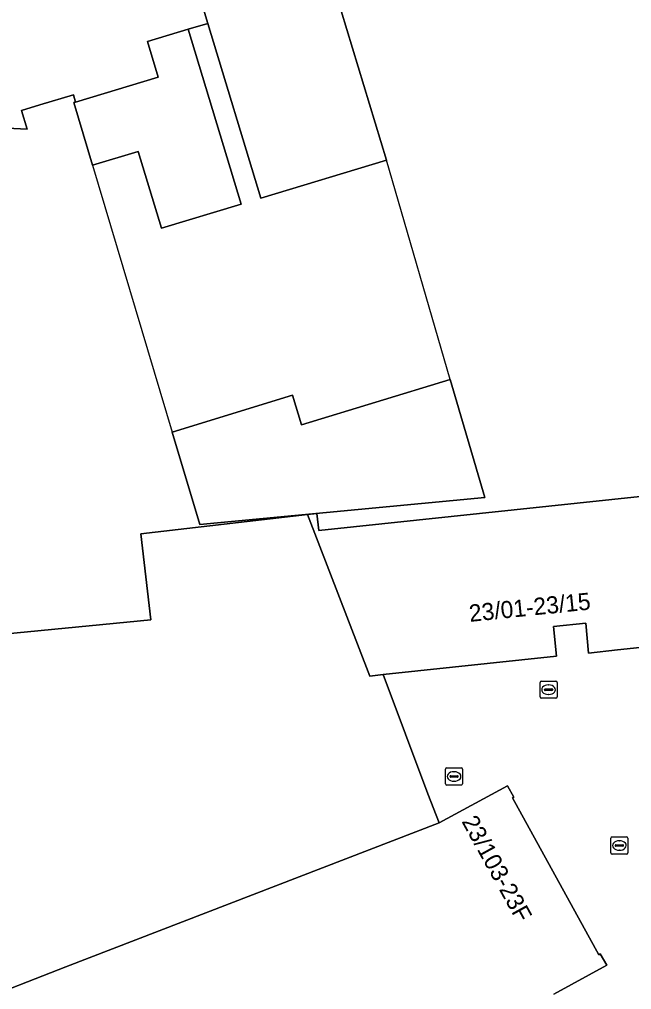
# Model space of a CAD drawing. Extents: x 161087 to 161926, y 382572 to 383873.
# Drawn here: x 161757.6 to 161793.5, y 382757.7 to 382814.4 of the extents above; entities that cross this region are included whole.
import ezdxf

# ---------------------------------------------------------------- set-up
doc = ezdxf.new("R2010")
doc.units = 0
for name, color, linetype in [('IMGEO_Brandkraan', 7, 'Continuous'), ('IMGEO_Erf', 7, 'Continuous'), ('IMGEO_Kolk', 7, 'Continuous'), ('IMGEO_Pand', 7, 'Continuous'), ('IMGEO_Pand_nummerreeks', 7, 'Continuous'), ('IMGEO_Pand_overbouw', 7, 'Continuous')]:
    doc.layers.add(name, color=color, linetype=linetype)

msp = doc.modelspace()

# ---------------------------------------------------------------- linework, layer by layer
at = {"layer": 'IMGEO_Brandkraan'}
for p, q in [((161782.57, 382769.723), (161782.57, 382770.575)), ((161782.645, 382770.649), (161783.497, 382770.649)), ((161783.571, 382770.575), (161783.571, 382769.723)), ((161782.829, 382770.143), (161782.829, 382770.155)), ((161783.267, 382770.106), (161782.869, 382770.106)), ((161782.872, 382770.192), (161783.27, 382770.192)), ((161783.058, 382770.429), (161783.083, 382770.429)), ((161783.313, 382770.155), (161783.313, 382770.143)), ((161783.497, 382769.649), (161782.645, 382769.649)), ((161783.081, 382769.869), (161783.056, 382769.869))]:
    msp.add_line(p, q, dxfattribs=at)
for points in [[(161782.57, 382769.723), (161782.57, 382770.575)], [(161782.645, 382770.649), (161783.497, 382770.649)], [(161783.571, 382770.575), (161783.571, 382769.723)], [(161783.497, 382769.649), (161782.645, 382769.649)]]:
    msp.add_lwpolyline(points, dxfattribs=at)
for centre, radius, start, end in [((161782.647, 382770.573), 0.0765, 91.552, 178.448), ((161782.647, 382770.573), 0.0765, 91.552, 178.448), ((161783.495, 382770.573), 0.0765, 1.552, 88.448), ((161783.495, 382770.573), 0.0765, 1.552, 88.448), ((161782.869, 382770.152), 0.0403, 85.8775, 175.7526), ((161782.866, 382770.142), 0.0366, 178.938, 274.7102), ((161783.27, 382770.149), 0.043, 264.8664, 352.4533), ((161783.274, 382770.154), 0.0386, 1.7309, 96.639), ((161782.647, 382769.725), 0.0765, 181.552, 268.448), ((161782.647, 382769.725), 0.0765, 181.552, 268.448), ((161783.495, 382769.725), 0.0765, 271.552, 358.448), ((161783.495, 382769.725), 0.0765, 271.552, 358.448)]:
    msp.add_arc(centre, radius, start, end, dxfattribs=at)
for centre, major_axis, ratio, start_param, end_param in [((161783.057, 382770.149), (-0.387, 0.002), 0.722429, 4.712389, 7.853982), ((161783.082, 382770.149), (-0.39, 0.002), 0.717154, 1.570796, 4.712389)]:
    msp.add_ellipse(centre, major_axis=major_axis, ratio=ratio, start_param=start_param, end_param=end_param, dxfattribs=at)
at = {"layer": 'IMGEO_Erf'}
for points in [[(161774.81, 382820.403), (161779.113, 382806.206), (161771.772, 382803.981), (161768.675, 382814.202), (161767.527, 382813.855), (161770.624, 382803.633), (161765.961, 382802.214), (161764.589, 382806.71), (161761.93, 382805.898), (161760.835, 382809.568), (161760.931, 382809.597), (161760.805, 382810.018), (161758.841, 382809.432), (161757.768, 382809.112), (161758.096, 382808.012), (161750.203, 382808.397)], [(161753.095, 382778.125), (161765.335, 382779.309), (161764.744, 382784.333), (161774.502, 382785.469), (161775.045, 382785.532), (161775.16, 382784.545), (161798.007, 382786.96)], [(161800.826, 382778.409), (161792.635, 382777.549), (161790.941, 382777.371), (161790.774, 382779.12), (161788.885, 382778.92), (161789.069, 382777.178), (161778.916, 382776.105), (161781.539, 382769.143), (161782.19, 382767.438), (161786.19, 382769.61), (161786.559, 382768.943), (161786.48, 382768.892), (161791.534, 382759.721), (161791.62, 382759.771), (161792.002, 382759.112), (161788.908, 382757.413)]]:
    msp.add_lwpolyline(points, dxfattribs=at)
msp.add_lwpolyline([(161768.198, 382784.893), (161766.586, 382790.298), (161773.62, 382792.444), (161774.146, 382790.723), (161782.85, 382793.379), (161784.864, 382786.465)], close=True, dxfattribs=at)
at = {"layer": 'IMGEO_Kolk'}
for p, q in [((161788.097, 382774.799), (161788.097, 382775.651)), ((161788.172, 382775.725), (161789.024, 382775.725)), ((161789.098, 382775.651), (161789.098, 382774.799)), ((161788.356, 382775.219), (161788.356, 382775.231)), ((161788.794, 382775.182), (161788.396, 382775.182)), ((161788.399, 382775.268), (161788.797, 382775.268)), ((161788.585, 382775.505), (161788.61, 382775.505)), ((161788.84, 382775.231), (161788.84, 382775.219)), ((161789.024, 382774.725), (161788.172, 382774.725)), ((161788.608, 382774.945), (161788.583, 382774.945)), ((161792.311, 382766.611), (161793.163, 382766.611)), ((161792.236, 382765.685), (161792.236, 382766.537)), ((161792.495, 382766.105), (161792.495, 382766.117)), ((161792.933, 382766.068), (161792.535, 382766.068)), ((161792.538, 382766.154), (161792.936, 382766.154)), ((161792.724, 382766.391), (161792.749, 382766.391)), ((161792.979, 382766.117), (161792.979, 382766.105)), ((161793.237, 382766.537), (161793.237, 382765.685)), ((161793.163, 382765.611), (161792.311, 382765.611)), ((161792.747, 382765.831), (161792.722, 382765.831))]:
    msp.add_line(p, q, dxfattribs=at)
for points in [[(161788.097, 382774.799), (161788.097, 382775.651)], [(161788.172, 382775.725), (161789.024, 382775.725)], [(161789.098, 382775.651), (161789.098, 382774.799)], [(161789.024, 382774.725), (161788.172, 382774.725)], [(161792.311, 382766.611), (161793.163, 382766.611)], [(161792.236, 382765.685), (161792.236, 382766.537)], [(161793.237, 382766.537), (161793.237, 382765.685)], [(161793.163, 382765.611), (161792.311, 382765.611)]]:
    msp.add_lwpolyline(points, dxfattribs=at)
for centre, radius, start, end in [((161788.174, 382775.649), 0.0765, 91.552, 178.448), ((161788.174, 382775.649), 0.0765, 91.552, 178.448), ((161789.022, 382775.649), 0.0765, 1.552, 88.448), ((161789.022, 382775.649), 0.0765, 1.552, 88.448), ((161788.396, 382775.228), 0.0403, 85.8775, 175.7526), ((161788.393, 382775.218), 0.0366, 178.938, 274.7102), ((161788.797, 382775.225), 0.043, 264.8664, 352.4533), ((161788.801, 382775.23), 0.0386, 1.7309, 96.639), ((161788.174, 382774.801), 0.0765, 181.552, 268.448), ((161788.174, 382774.801), 0.0765, 181.552, 268.448), ((161789.022, 382774.801), 0.0765, 271.552, 358.448), ((161789.022, 382774.801), 0.0765, 271.552, 358.448), ((161792.313, 382766.535), 0.0765, 91.552, 178.448), ((161792.313, 382766.535), 0.0765, 91.552, 178.448), ((161793.161, 382766.535), 0.0765, 1.552, 88.448), ((161793.161, 382766.535), 0.0765, 1.552, 88.448), ((161792.535, 382766.114), 0.0403, 85.8775, 175.7526), ((161792.532, 382766.104), 0.0366, 178.938, 274.7102), ((161792.936, 382766.111), 0.043, 264.8664, 352.4533), ((161792.94, 382766.116), 0.0386, 1.7309, 96.639), ((161792.313, 382765.687), 0.0765, 181.552, 268.448), ((161792.313, 382765.687), 0.0765, 181.552, 268.448), ((161793.161, 382765.687), 0.0765, 271.552, 358.448), ((161793.161, 382765.687), 0.0765, 271.552, 358.448)]:
    msp.add_arc(centre, radius, start, end, dxfattribs=at)
for centre, major_axis, ratio, start_param, end_param in [((161788.584, 382775.225), (-0.387, 0.002), 0.722429, 4.712389, 7.853982), ((161788.609, 382775.225), (-0.39, 0.002), 0.717154, 1.570796, 4.712389), ((161792.723, 382766.111), (-0.387, 0.002), 0.722429, 4.712389, 7.853982), ((161792.748, 382766.111), (-0.39, 0.002), 0.717154, 1.570796, 4.712389)]:
    msp.add_ellipse(centre, major_axis=major_axis, ratio=ratio, start_param=start_param, end_param=end_param, dxfattribs=at)
at = {"layer": 'IMGEO_Pand'}
for points in [[(161774.81, 382820.403), (161774.63, 382820.361), (161773.652, 382823.531), (161769.297, 382822.242), (161765.834, 382821.218), (161765.388, 382822.546), (161765.346, 382822.671), (161765.152, 382822.617), (161765.13, 382816.764), (161767.666, 382817.533), (161767.689, 382817.455), (161768.675, 382814.202), (161771.772, 382803.981), (161779.113, 382806.206)], [(161767.527, 382813.855), (161768.675, 382814.202), (161767.689, 382817.455), (161767.666, 382817.533), (161765.13, 382816.764), (161765.152, 382822.617), (161764.869, 382822.537), (161764.841, 382822.53), (161764.78, 382822.713), (161741.914, 382815.103), (161737.983, 382813.795), (161737.9, 382813.764), (161739.444, 382809.112), (161750.203, 382808.397), (161758.096, 382808.012), (161757.768, 382809.112), (161758.841, 382809.432), (161760.805, 382810.018), (161760.931, 382809.597), (161765.771, 382811.063), (161765.144, 382813.132)], [(161767.527, 382813.855), (161765.144, 382813.132), (161765.771, 382811.063), (161760.931, 382809.597), (161760.835, 382809.568), (161761.93, 382805.898), (161764.589, 382806.71), (161765.961, 382802.214), (161770.624, 382803.633)], [(161782.85, 382793.379), (161774.146, 382790.723), (161773.62, 382792.444), (161766.586, 382790.298), (161768.198, 382784.893), (161784.864, 382786.465)], [(161778.916, 382776.105), (161789.069, 382777.178), (161788.885, 382778.92), (161790.774, 382779.12), (161790.941, 382777.371), (161792.635, 382777.549), (161800.826, 382778.409), (161802.432, 382778.578), (161798.007, 382786.96), (161775.16, 382784.545), (161775.045, 382785.532), (161774.502, 382785.469), (161778.137, 382776.023)], [(161778.916, 382776.105), (161778.137, 382776.023), (161774.502, 382785.469), (161764.744, 382784.333), (161765.335, 382779.309), (161753.095, 382778.125), (161744.443, 382777.251), (161737.071, 382774.806), (161737.155, 382774.582), (161736.997, 382774.519), (161739.569, 382768.038), (161740.865, 382764.716), (161742.992, 382759.27), (161745.004, 382754.118), (161754.496, 382757.83), (161754.87, 382756.874), (161760.362, 382759.021), (161782.19, 382767.438), (161781.539, 382769.143)]]:
    msp.add_lwpolyline(points, close=True, dxfattribs=at)
msp.add_lwpolyline([(161788.908, 382757.413), (161792.002, 382759.112), (161791.62, 382759.771), (161791.534, 382759.721), (161786.48, 382768.892), (161786.559, 382768.943), (161786.19, 382769.61), (161782.19, 382767.438), (161760.362, 382759.021), (161754.87, 382756.874), (161754.496, 382757.83), (161745.004, 382754.118)], dxfattribs=at)
at = {"layer": 'IMGEO_Pand_overbouw'}
msp.add_lwpolyline([(161779.113, 382806.206), (161771.772, 382803.981), (161768.675, 382814.202), (161767.527, 382813.855), (161770.624, 382803.633), (161765.961, 382802.214), (161764.589, 382806.71), (161761.93, 382805.898), (161766.586, 382790.298), (161773.62, 382792.444), (161774.146, 382790.723), (161782.85, 382793.379)], close=True, dxfattribs=at)

# ---------------------------------------------------------------- texts
at = {"layer": 'IMGEO_Pand_nummerreeks'}
for s, rotation, p in [('23/01-23/15', 5.8715, (161783.995, 382779.19)), ('23/103-23F', 298.8539, (161783.49, 382767.523))]:
    msp.add_text(s, height=1, rotation=rotation, dxfattribs=at).set_placement(p)

doc.saveas('drawing.dxf')
